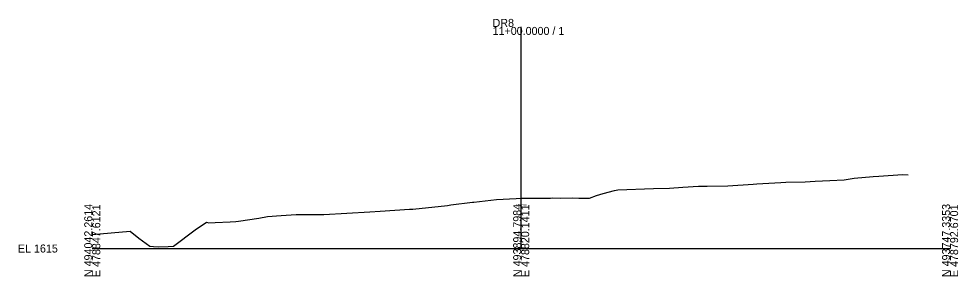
# Model space of a CAD drawing. Extents: x 24 to 353, y -10 to 3552.
# Drawn here: x 24.3 to 352.8, y 990.3 to 1080.4 of the extents above; entities that cross this region are included whole.
import ezdxf

# ---------------------------------------------------------------- set-up
doc = ezdxf.new("R2010")
doc.units = 0
for name, color, linetype in [('Exist Cross Section Cell', 7, 'Continuous'), ('Exist XS Center Line Elevation Label', 7, 'Continuous'), ('Exist XS Ground Line', 7, 'Continuous'), ('Scratch_Level_5', 7, 'Continuous')]:
    doc.layers.add(name, color=color, linetype=linetype)

msp = doc.modelspace()

# ---------------------------------------------------------------- linework, layer by layer
at = {"layer": 'Exist Cross Section Cell'}
for p, q in [((200, 1000), (200, 1077.52)), ((50, 1000), (200, 1000)), ((200, 1000), (350, 1000))]:
    msp.add_line(p, q, dxfattribs=at)
at = {"layer": 'Exist XS Ground Line'}
msp.add_lwpolyline([(50, 1004.92), (63.3, 1006.04), (66.26, 1003.67), (70.1, 1000.82), (71.37, 1000.72), (73.09, 1000.59), (76.52, 1000.76), (78.39, 1000.81), (85.98, 1006.56), (89.98, 1009.21), (90.79, 1009.01), (92.96, 1009.11), (98.25, 1009.38), (100.25, 1009.49), (101.16, 1009.52), (108.31, 1010.66), (111.32, 1011.25), (116.09, 1011.59), (121.27, 1011.85), (130.93, 1011.95), (147.04, 1012.85), (150.72, 1013.02), (160.95, 1013.74), (162.09, 1013.81), (174.27, 1015.1), (175.35, 1015.23), (183.01, 1016.16), (183.47, 1016.21), (191.42, 1017.1), (198.26, 1017.48), (200, 1017.56), (201.6, 1017.64), (203.66, 1017.61), (210.22, 1017.59), (210.89, 1017.67), (213.85, 1017.6), (217.95, 1017.72), (220.11, 1017.66), (223.89, 1017.6), (226.34, 1018.53), (228.73, 1019.28), (232.61, 1020.31), (233.76, 1020.56), (246.33, 1020.97), (251.89, 1021.13), (256.48, 1021.43), (262.07, 1021.78), (265.06, 1021.85), (272.24, 1021.96), (281.09, 1022.51), (282.42, 1022.6), (290.78, 1023.05), (292.59, 1023.17), (299.36, 1023.38), (302.76, 1023.53), (307.94, 1023.76), (312.94, 1024.08), (316.51, 1024.56), (323.11, 1025.15), (325.09, 1025.33), (333.39, 1025.84), (335.34, 1025.82)], dxfattribs=at)
at = {"layer": 'Scratch_Level_5'}
msp.add_lwpolyline([(50, 1004.92), (63.3, 1006.04), (66.26, 1003.67), (70.1, 1000.82), (71.37, 1000.72), (73.09, 1000.59), (76.52, 1000.76), (78.39, 1000.81), (85.98, 1006.56), (89.98, 1009.21), (90.79, 1009.01), (92.96, 1009.11), (98.25, 1009.38), (100.25, 1009.49), (101.16, 1009.52), (108.31, 1010.66), (111.32, 1011.25), (116.09, 1011.59), (121.27, 1011.85), (130.93, 1011.95), (147.04, 1012.85), (150.72, 1013.02), (160.95, 1013.74), (162.09, 1013.81), (174.27, 1015.1), (175.35, 1015.23), (183.01, 1016.16), (183.47, 1016.21), (191.42, 1017.1), (198.26, 1017.48), (200, 1017.56), (201.6, 1017.64), (203.66, 1017.61), (210.22, 1017.59), (210.89, 1017.67), (213.85, 1017.6), (217.95, 1017.72), (220.11, 1017.66), (223.89, 1017.6), (226.34, 1018.53), (228.73, 1019.28), (232.61, 1020.31), (233.76, 1020.56), (246.33, 1020.97), (251.89, 1021.13), (256.48, 1021.43), (262.07, 1021.78), (265.06, 1021.85), (272.24, 1021.96), (281.09, 1022.51), (282.42, 1022.6), (290.78, 1023.05), (292.59, 1023.17), (299.36, 1023.38), (302.76, 1023.53), (307.94, 1023.76), (312.94, 1024.08), (316.51, 1024.56), (323.11, 1025.15), (325.09, 1025.33), (333.39, 1025.84), (335.34, 1025.82)], dxfattribs=at)

# ---------------------------------------------------------------- texts
at = {"layer": 'Exist Cross Section Cell'}
for s, p in [('11+00.0000 / 1', (190, 1074.72)), ('DR8', (190, 1077.52)), ('EL 1615', (24, 998.6))]:
    msp.add_text(s, height=2.8, dxfattribs=at).set_placement(p)
for s, p in [('N 494042.2614', (50, 990)), ('E 478847.6121', (52.8, 990)), ('N 493894.7984', (200, 990)), ('E 478820.1411', (202.8, 990)), ('N 493747.3353', (350, 990)), ('E 478792.6701', (352.8, 990))]:
    msp.add_text(s, height=2.8, rotation=90, dxfattribs=at).set_placement(p)
at = {"layer": 'Exist XS Center Line Elevation Label'}
msp.add_text('1632.56', height=0.75, dxfattribs=at).set_placement((198.19, 1014.81))

doc.saveas('drawing.dxf')
